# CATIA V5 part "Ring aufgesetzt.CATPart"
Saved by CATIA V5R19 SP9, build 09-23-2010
Part number: Ring aufgesetzt
Bounding box of the stored display mesh (mm): x -19.987 to 19.987, y -10 to 67, z 0 to 10
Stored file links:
  C:\Users\user\Desktop\Ring aufgesetzt.CATPart
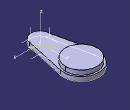
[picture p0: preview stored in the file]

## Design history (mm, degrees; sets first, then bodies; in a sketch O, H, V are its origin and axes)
AxisSystem1: origin (0, 0, 0), X (1, 0, 0), Y (0, 1, 0), Z (0, 0, 1)
Set1
  Sketch1 on XY plane of AxisSystem1, origin (0, 0, 0), H (1, 0, 0), V (0, 1, 0)
    line L1 (19.5421, 42.7447) -> (9.771, -2.1277)
    line L2 (-19.5421, 42.7447) -> (-9.771, -2.1277)
    arc A1 centre (0, 47) radius 20 from (19.5421, 42.7447) to (-19.5421, 42.7447) ccw
    point P1 (0, 47)
    arc A2 centre (0, 0) radius 10 from (-9.771, -2.1277) to (9.771, -2.1277) ccw
    distance H P1 = 47
    radius A2 = 10
    radius A1 = 20
    tangency: L1 A1, L2 A1, L1 A2, A2 L2
    coincidence: P1 V
Body1 (main body)
  Body2
    Pad1: profile Sketch1, direction (0, 0, 1), length 5
  Add1: tool Body2
  Body3
    Sketch2 on XY plane of AxisSystem1, origin (0, 0, 0), H (1, 0, 0), V (0, 1, 0)
      reference projected arc E1 centre (0, 47) radius 20 from (19.5421, 42.7447) to (-19.5421, 42.7447) ccw from Sketch1.A1
      circle A1 centre (0, 47) radius 18
      point P3 (0, 47)
      distance E1 A1 = 2
      concentricity: P3 E1
    Pad2: profile Sketch2, direction (0, 0, 1), length 10
  Add2: tool Body3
